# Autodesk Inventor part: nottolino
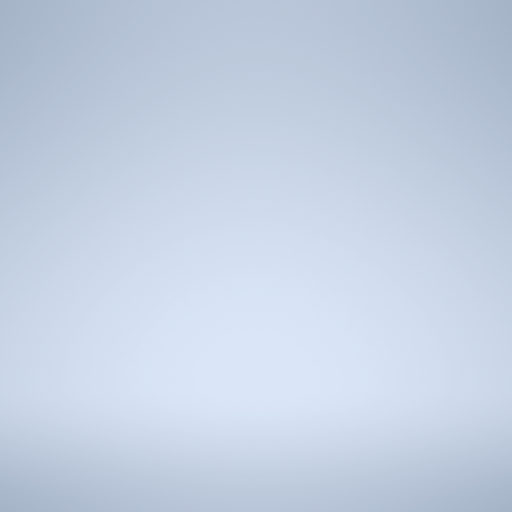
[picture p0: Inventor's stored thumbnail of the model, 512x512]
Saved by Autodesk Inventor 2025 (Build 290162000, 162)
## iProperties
Created: 2025-10
Part Number: nottolino
Material: Generico
Document SubType Name: Modeling
Designer: 18619647
Density: 1 g/cm^3
Appearance: Default
Author: 18619647
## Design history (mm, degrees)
